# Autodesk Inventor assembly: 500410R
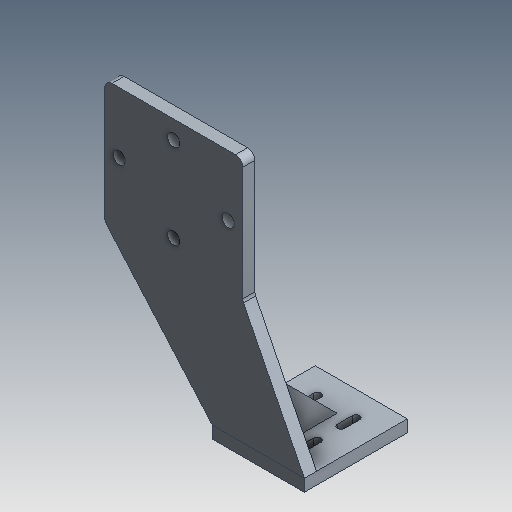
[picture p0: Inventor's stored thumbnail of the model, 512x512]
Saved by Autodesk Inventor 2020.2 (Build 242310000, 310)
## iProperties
Created: 2000-01
Part Number: 500410R
Description: WMT-CP,FA,XX,TRANSFER PLATE,HORIZ BLANK ADVANCE
Document SubType Name: Assembly
Designer: sspink
Mass: 813.891 g
Surface Area: 768.263 cm^2
Volume: 300.329 cm^3
Density: 2.71 g/cm^3
Control State: 0
Checked Out: False
Master: False
Shininess: 0.0
Length Units: 11269
Angle Units: 11279
Time Units: 11290
Mass Units: 11283
Length Display Precision: 3
Angle Display Precision: 2
Compacted: True
Dimensions: 213x85x164,9 mm
Mass: 0,814 kg
DocNumber: 500410R.iam
Folder: 01 - Themengebiete\Simplification\01 - Packaging machine\
VDS_Category: 3D Komponenten
Density: 0.0
Volumn: 0.0
Area: 0.0
PropertySet Name: Model Information
Author: sspink
Revision Number: -
Title: 500410R
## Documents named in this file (5)
- D:\07 - DEMODATEN\OTX 2019 - Dataset - UPDATE - Dez2019\Designs\07-Packing machine\500410R.iam
- D:\07 - DEMODATEN\OTX 2019 - Dataset - UPDATE - Dez2019\Designs\07-Packing machine\Parts\ADSK-011387.ipt
- D:\07 - DEMODATEN\OTX 2019 - Dataset - UPDATE - Dez2019\Designs\07-Packing machine\Parts\ADSK-011388.ipt
- D:\07 - DEMODATEN\OTX 2019 - Dataset - UPDATE - Dez2019\Designs\07-Packing machine\Parts\ADSK-011389.ipt
- D:\07 - DEMODATEN\OTX 2019 - Dataset - UPDATE - Dez2019\Designs\07-Packing machine\Parts\ADSK-011390.ipt
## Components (5 placed, 4 different names)
1. ADSK-011387:1 — Mate:1, Mate:3, Mate:5, Mate:6, Mate:7, Mate:8, Mate:9, Flush:3, Passend:10, Fluchtend:5
2. ADSK-011390:2 — Mate:8, Mate:9, Flush:3
3. ADSK-011388:1 — Mate:1, Mate:4, Fluchtend:4, Passend:10, Fluchtend:5
4. ADSK-011389:1 — Mate:3, Mate:4, Fluchtend:4
5. ADSK-011390:1 — Mate:5, Mate:6, Mate:7
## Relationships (12: Mate 9, Flush 3)
- Mate:1: ADSK-011387:1 ↔ ADSK-011388:1
- Mate:3: ADSK-011387:1 ↔ ADSK-011389:1
- Mate:4: ADSK-011388:1 ↔ ADSK-011389:1
- Mate:5: ADSK-011387:1 ↔ ADSK-011390:1
- Mate:6: ADSK-011387:1 ↔ ADSK-011390:1
- Mate:7: ADSK-011387:1 ↔ ADSK-011390:1
- Mate:8: ADSK-011387:1 ↔ ADSK-011390:2
- Mate:9: ADSK-011387:1 ↔ ADSK-011390:2
- Flush:3: ADSK-011387:1 ↔ ADSK-011390:2
- Fluchtend:4 [Flush]: ADSK-011388:1 ↔ ADSK-011389:1
- Passend:10 [Mate]: ADSK-011387:1 ↔ ADSK-011388:1
- Fluchtend:5 [Flush]: ADSK-011387:1 ↔ ADSK-011388:1
